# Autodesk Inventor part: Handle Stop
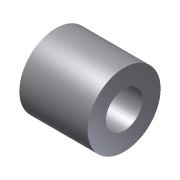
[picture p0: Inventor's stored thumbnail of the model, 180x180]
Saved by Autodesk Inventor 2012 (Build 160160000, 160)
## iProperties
Shininess: 77.0
Length Units: 11269
Angle Units: 11279
Time Units: 11290
Mass Units: 11283
Length Display Precision: 3
Angle Display Precision: 2
Compacted: True
Created: 2002-02
Part Number: Handle Stop
Document SubType Name: Modeling
Designer: ***
Density: 1 g/cm^3
Material: Default
Density: 0.0
Volumn: 0.0
Area: 0.0
PropertySet Name: Model Information
Control State: 0
Master: False
Checked Out: False
Author: ***
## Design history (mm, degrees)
sketch "Sketch1"
  geometry: L1 (0, 0)-(0, -2); L2 (0, -2)-(8, -2); L3 (8, -2)-(8, 13); L4 (8, 13)-(4, 13); L5 (4, 13)-(4, 0); L6 (4, 0)-(0, 0)
  constraints: 12 end point, 4 parallel, 1 perpendicular, 1 vertical
  dimensions: "d0" = 16 diameter of L3 L1; "d1" = 8 diameter of L5 L1; "d2" = 2 distance of L1.start L1.end; "d3" = 15 distance of L2.end L3.end
revolve "Revolution1" sketch "Sketch1" stored, may be unused: angle "d4" = 90 deg
body "Solid1"
